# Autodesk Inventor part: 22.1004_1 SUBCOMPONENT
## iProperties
Created: 2011-07
Part Number: 22.1004_1 SUBCOMPONENT
Document SubType Name: Modeling
Designer: Administrator
Density: 1.06 g/cm^3
Description: END CAP 45X45 GRAY SUBCOMPONENT
Material: ABS Plastic
Mass: 5.95369 g
Surface Area: 62.6048 cm^2
Volume: 5.61669 cm^3
Author: Administrator
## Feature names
1. Base1
